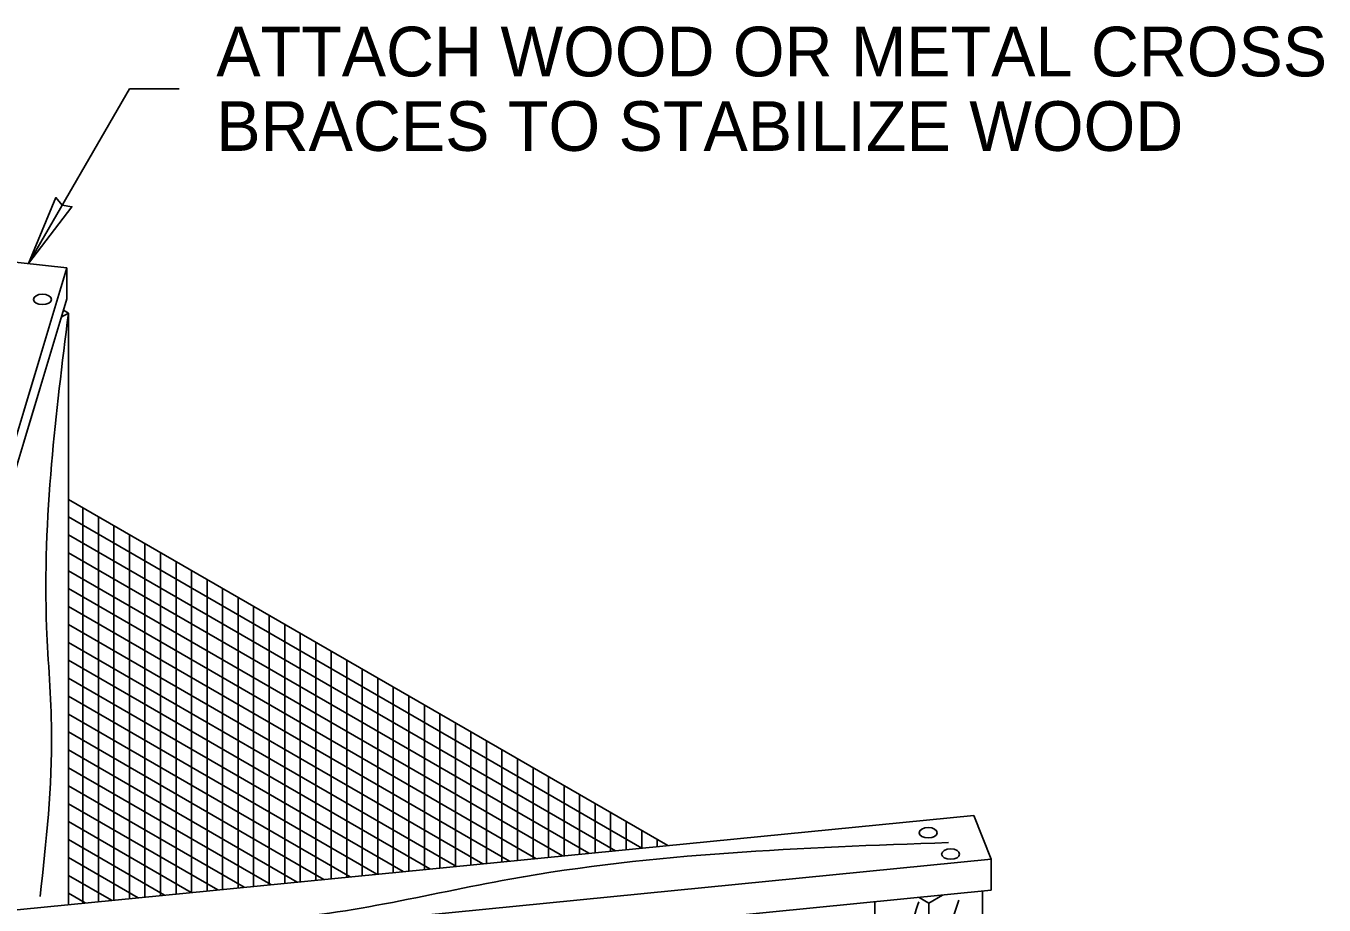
# Model space of a CAD drawing. Extents: x 99862 to 103151, y 100000 to 102076.
# Drawn here: x 102097.1 to 102515.2, y 100780.2 to 101063.3 of the extents above; entities that cross this region are included whole.
import ezdxf

# ---------------------------------------------------------------- set-up
doc = ezdxf.new("R2010")
doc.units = 0
for name, color, linetype in [('Level 15', 7, 'Continuous'), ('Level 2', 7, 'Continuous'), ('Level 20', 7, 'Continuous'), ('Level 3', 7, 'Continuous'), ('Level 6', 7, 'Continuous'), ('Level 9', 7, 'Continuous')]:
    doc.layers.add(name, color=color, linetype=linetype)

msp = doc.modelspace()

# ---------------------------------------------------------------- linework, layer by layer
at = {"layer": 'Level 15'}
for p in [(102097.89, 100986.8), (102146.39, 101043.09)]:
    msp.add_line(p, (102130.39, 101043.09), dxfattribs=at)
msp.add_lwpolyline([(102097.89, 100986.8), (102111.89, 101005.07), (102108.78, 101005.65), (102106.72, 101008.06)], close=True, dxfattribs=at)
at = {"layer": 'Level 2'}
for centre in [(102102.38, 100975.26), (102387.7, 100803.45), (102394.93, 100796.58)]:
    msp.add_ellipse(centre, major_axis=(2.9, 0), ratio=0.57735, dxfattribs=at)
at = {"layer": 'Level 3'}
for p, q in [((102110.75, 100910.82), (102303.83, 100799.35)), ((102110.75, 100905.2), (102295.5, 100798.53)), ((102115.41, 100780.77), (102115.41, 100908.13)), ((102120.41, 100781.27), (102120.41, 100905.24)), ((102125.41, 100781.76), (102125.41, 100902.36)), ((102110.75, 100899.42), (102286.96, 100797.68)), ((102130.41, 100782.25), (102130.41, 100899.47)), ((102110.75, 100893.65), (102278.42, 100796.84)), ((102135.41, 100782.75), (102135.41, 100896.58)), ((102140.41, 100783.24), (102140.41, 100893.7)), ((102145.41, 100783.73), (102145.41, 100890.81)), ((102110.75, 100887.87), (102269.88, 100796)), ((102150.41, 100784.22), (102150.41, 100887.92)), ((102155.41, 100784.72), (102155.41, 100885.04)), ((102110.75, 100882.1), (102261.34, 100795.16)), ((102160.41, 100785.21), (102160.41, 100882.15)), ((102110.75, 100876.33), (102252.8, 100794.32)), ((102165.41, 100785.7), (102165.41, 100879.26)), ((102170.41, 100786.2), (102170.41, 100876.38)), ((102175.41, 100786.69), (102175.41, 100873.49)), ((102110.75, 100870.55), (102244.25, 100793.47)), ((102180.41, 100787.18), (102180.41, 100870.6)), ((102185.41, 100787.67), (102185.41, 100867.72)), ((102110.75, 100864.78), (102235.71, 100792.63)), ((102190.41, 100788.17), (102190.41, 100864.83)), ((102195.41, 100788.66), (102195.41, 100861.94)), ((102110.75, 100859.01), (102227.17, 100791.79)), ((102200.41, 100789.15), (102200.41, 100859.06)), ((102205.41, 100789.65), (102205.41, 100856.17)), ((102110.75, 100853.23), (102218.63, 100790.95)), ((102210.41, 100790.14), (102210.41, 100853.28)), ((102110.75, 100847.46), (102210.09, 100790.11)), ((102215.41, 100790.63), (102215.41, 100850.4)), ((102220.41, 100791.12), (102220.41, 100847.51)), ((102225.41, 100791.62), (102225.41, 100844.62)), ((102110.75, 100841.69), (102201.55, 100789.26)), ((102230.41, 100792.11), (102230.41, 100841.74)), ((102235.41, 100792.6), (102235.41, 100838.85)), ((102110.75, 100835.91), (102193, 100788.42)), ((102240.41, 100793.1), (102240.41, 100835.96)), ((102110.75, 100830.14), (102184.46, 100787.58)), ((102245.41, 100793.59), (102245.41, 100833.07)), ((102250.41, 100794.08), (102250.41, 100830.19)), ((102255.41, 100794.57), (102255.41, 100827.3)), ((102110.75, 100824.37), (102175.92, 100786.74)), ((102260.41, 100795.07), (102260.41, 100824.41)), ((102265.41, 100795.56), (102265.41, 100821.53)), ((102110.75, 100818.59), (102167.38, 100785.9)), ((102270.41, 100796.05), (102270.41, 100818.64)), ((102275.41, 100796.55), (102275.41, 100815.75)), ((102110.75, 100812.82), (102158.84, 100785.05)), ((102280.41, 100797.04), (102280.41, 100812.87)), ((102285.41, 100797.53), (102285.41, 100809.98)), ((102110.75, 100807.05), (102150.3, 100784.21)), ((102290.41, 100798.02), (102290.41, 100807.09)), ((102110.75, 100801.27), (102141.75, 100783.37)), ((102295.41, 100798.52), (102295.41, 100804.21)), ((102300.41, 100799.01), (102300.41, 100801.32)), ((102110.75, 100795.5), (102133.21, 100782.53)), ((102110.75, 100789.73), (102124.67, 100781.69)), ((102110.75, 100783.95), (102116.13, 100780.84))]:
    msp.add_line(p, q, dxfattribs=at)
at = {"layer": 'Level 6'}
for p, q in [((102110.25, 100985.46), (101980.36, 100553.63)), ((102085.52, 100988.13), (102110.25, 100985.46)), ((102110.25, 100975.46), (102110.25, 100985.46)), ((102110.25, 100975.46), (101980.36, 100543.63)), ((102049.75, 100774.3), (102402.35, 100809.06)), ((102402.35, 100809.06), (102407.94, 100794.91)), ((102045.19, 100759.15), (102407.94, 100794.91)), ((102407.94, 100784.91), (102407.94, 100794.91)), ((102042.09, 100748.85), (102407.94, 100784.91))]:
    msp.add_line(p, q, dxfattribs=at)
msp.add_spline([(102058.71, 100766.43), (102117.57, 100775.27), (102172.02, 100775.27), (102252.96, 100788.52), (102394.24, 100800.3)], degree=3, dxfattribs=at)
at = {"layer": 'Level 9'}
for p, q in [((102108.46, 100969.51), (102110.75, 100970.82)), ((102110.75, 100970.82), (102109.14, 100971.75)), ((102110.75, 100780.31), (102110.75, 100970.82)), ((102405.2, 100740.82), (102405.2, 100784.64)), ((102370.55, 100720.82), (102370.55, 100781.23)), ((102387.87, 100780.82), (102384.75, 100782.63)), ((102387.87, 100780.82), (102392.28, 100783.37)), ((102387.87, 100730.82), (102387.87, 100780.82))]:
    msp.add_line(p, q, dxfattribs=at)
for points in [[(102110.75, 100970.82), (102105.32, 100922.18), (102103.74, 100869.63), (102105.32, 100836.01), (102101.64, 100782.93)], [(102384.73, 100781.24), (102382.08, 100771.32), (102385.22, 100754.15)], [(102397.54, 100781.72), (102394.4, 100768.9), (102401.17, 100744.96)]]:
    msp.add_spline(points, degree=3, dxfattribs=at)

# ---------------------------------------------------------------- texts
at = {"layer": 'Level 20'}
for s, p in [('ATTACH WOOD OR METAL CROSS', (102158.39, 101047.09)), ('BRACES TO STABILIZE WOOD', (102158.39, 101023.09))]:
    msp.add_text(s, height=16, rotation=360, dxfattribs=at).set_placement(p)

doc.saveas('drawing.dxf')
